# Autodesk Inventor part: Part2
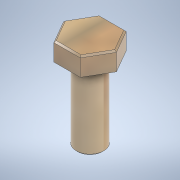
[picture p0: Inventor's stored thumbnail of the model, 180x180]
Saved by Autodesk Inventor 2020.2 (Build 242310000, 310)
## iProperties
Created: 2020-01
Part Number: Part2
Material: Wood (Maple)
Document SubType Name: Modeling
Designer: thira
Density: 0.67 g/cm^3
Appearance: Natural Maple - Glossy Dark Tint
Author: thira
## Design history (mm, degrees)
sketch "Sketch1"
  geometry: L1 (8.66, 0)-(4.33, -7.5); L2 (4.33, -7.5)-(-4.33, -7.5); L3 (-4.33, -7.5)-(-8.66, 0); L4 (-8.66, 0)-(-4.33, 7.5); L5 (-4.33, 7.5)-(4.33, 7.5); L6 (4.33, 7.5)-(8.66, 0); C1 r 4.5 at (0, 0); 2 further points
  constraints: 12 end point, 2 coincident, 1 centre point, 1 horizontal alignment, 13 other
  dimensions: "d0" = 15 distance between parallel lines of L2 L5; "d1" = 9 diameter of C1
extrude "Extrusion1" new body sketch "Sketch1" distance "d2" = 6; taper "d3" = 0 deg
extrude "Extrusion2" join sketch "Sketch1" distance "d4" = 25; taper "d5" = 0 deg
chamfer "Chamfer1" distance "d6" = 0.5; stored, may be unused: second distance "d7" = 2, angle "d8" = 45 deg
chamfer "Chamfer2" distance "d9" = 0.5; stored, may be unused: second distance "d10" = 2, angle "d11" = 45 deg
body "Solid1"
